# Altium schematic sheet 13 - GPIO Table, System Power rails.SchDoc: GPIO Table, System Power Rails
size A3; PageSetup: Record=PageOptions¦CenterHorizontal=True¦CenterVertical=True¦PrintScale=1.01¦XCorrection=1.00¦YCorrection=1.00¦PrintKind=0¦BorderSize=5000000¦LeftOffset=0¦BottomOffset=0¦Orientation=2¦PaperLength=4200¦PaperWidth=2970¦Scale=100¦PaperSource=15¦PrintQuality=600¦MediaType=1¦DitherType=10¦PrintScaleMode=1¦PaperKind=A3¦PaperIndex=8; Author: Sébastien MEYER; SheetNumber: 13; SheetTotal: 14
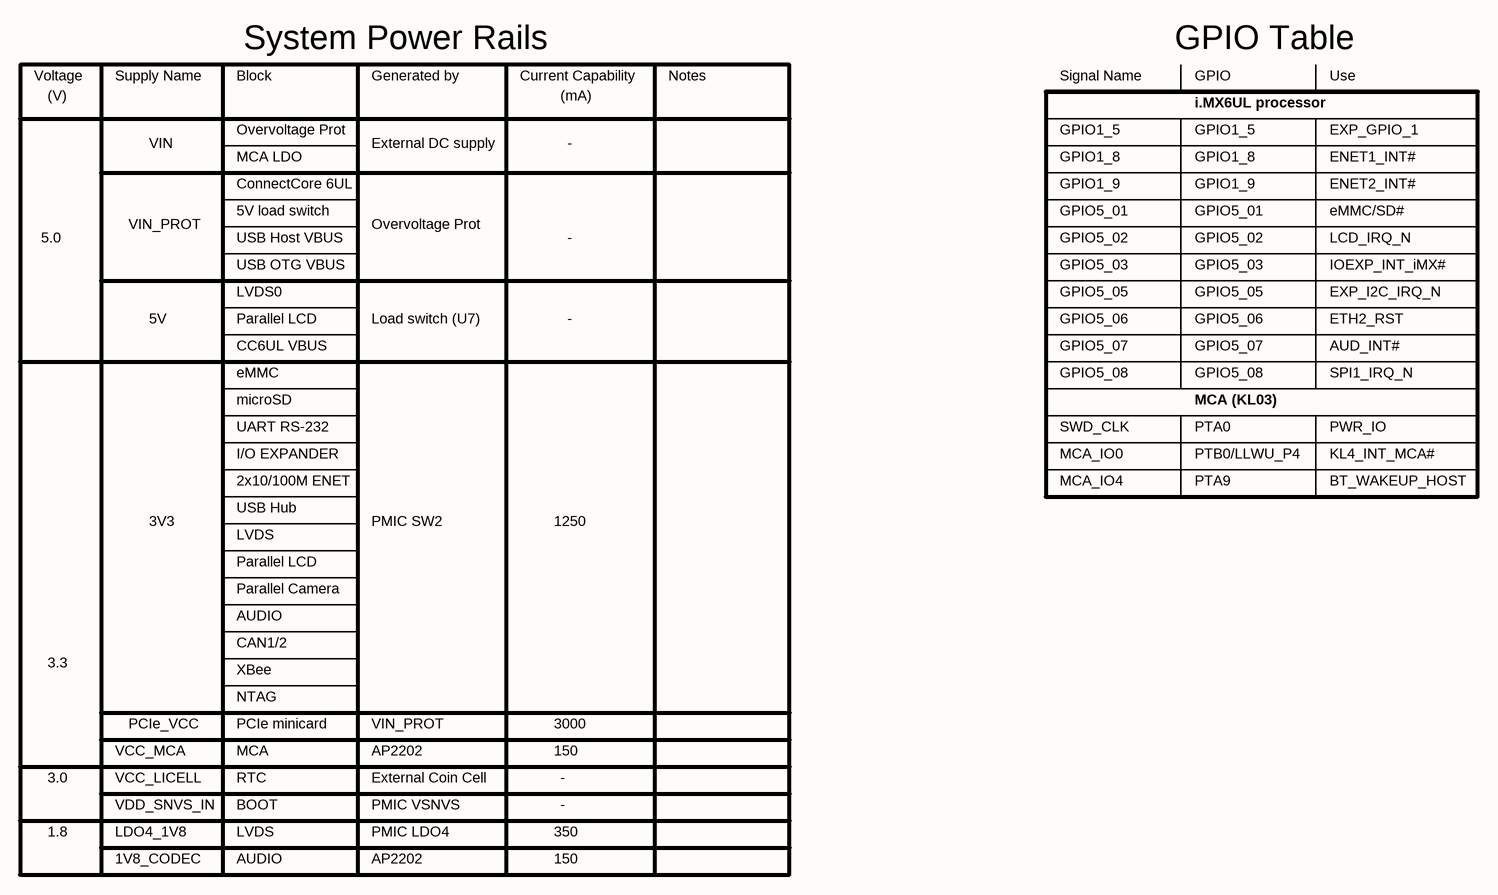
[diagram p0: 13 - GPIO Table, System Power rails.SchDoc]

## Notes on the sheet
- Voltage
- (V)
- Supply Name
- Block
- System Power Rails
- Generated by
- Current Capability
- (mA)
- Notes
- Signal Name
- GPIO Table
- GPIO
- i.MX6UL processor
- Use
- VIN
- Overvoltage Prot
- MCA LDO
- External DC supply
- -
- GPIO1_5
- GPIO1_8
- EXP_GPIO_1
- ENET1_INT#
- 5.0
- VIN_PROT
- USB Host VBUS
- ConnectCore 6UL
- 5V load switch
- GPIO1_9
- GPIO5_01
- GPIO5_02
- ENET2_INT#
- eMMC/SD#
- LCD_IRQ_N
- USB OTG VBUS
- LVDS0
- GPIO5_05
- GPIO5_03
- EXP_I2C_IRQ_N
- IOEXP_INT_iMX#
- 5V
- Parallel LCD
- eMMC
- CC6UL VBUS
- Load switch (U7)
- GPIO5_07
- GPIO5_08
- GPIO5_06
- AUD_INT#
- SPI1_IRQ_N
- ETH2_RST
- microSD
- UART RS-232
- SWD_CLK
- MCA (KL03)
- PTA0
- PWR_IO
- 3V3
- I/O EXPANDER
- 2x10/100M ENET
- USB Hub
- PMIC SW2
- 1250
- MCA_IO0
- MCA_IO4
- PTB0/LLWU_P4
- PTA9
- KL4_INT_MCA#
- BT_WAKEUP_HOST
- LVDS
- AUDIO
- CAN1/2
- Parallel Camera
- 3.3
- XBee
- NTAG
- 3.0
- VCC_MCA
- VCC_LICELL
- PCIe_VCC
- MCA
- RTC
- PCIe minicard
- AP2202
- External Coin Cell
- 150
- 3000
- 1.8
- LDO4_1V8
- VDD_SNVS_IN
- BOOT
- PMIC LDO4
- PMIC VSNVS
- 350
- 1V8_CODEC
